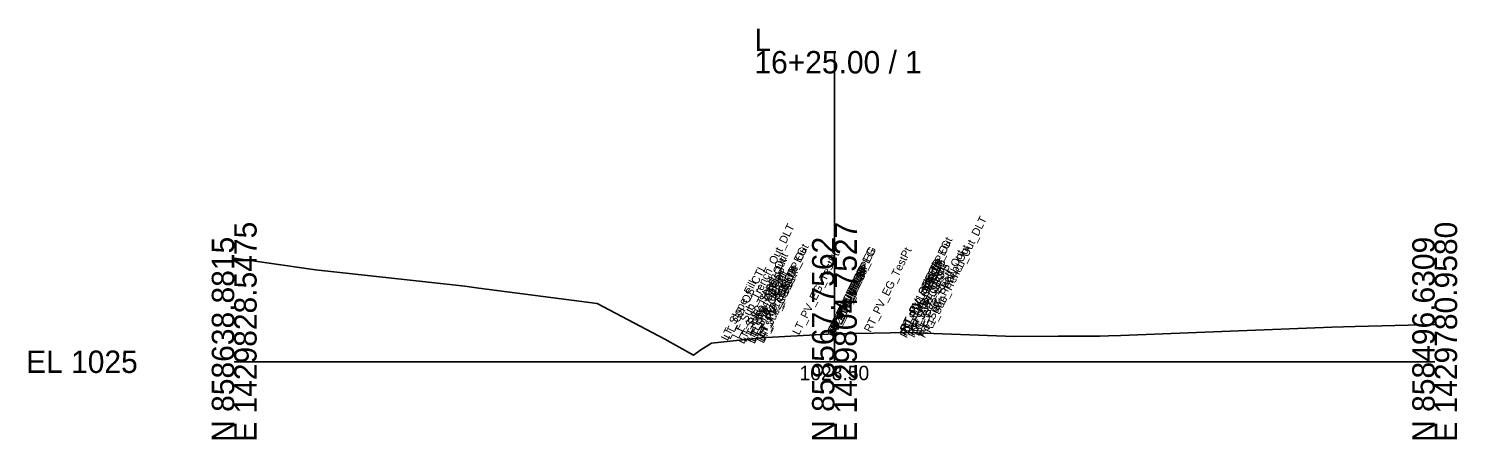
# Model space of a CAD drawing. Extents: x -26 to 176, y -10 to 13058.
# Drawn here: x -25.7 to 152.8, y 9490.3 to 9541.6 of the extents above; entities that cross this region are included whole.
import ezdxf

# ---------------------------------------------------------------- set-up
doc = ezdxf.new("R2010")
doc.units = 0
for name, color, linetype in [('Default', 7, 'Continuous'), ('Exist Cross Section Cell', 7, 'Continuous'), ('Exist XS Center Line Elevation Label', 7, 'Continuous'), ('Exist XS Ground Line', 7, 'Continuous'), ('Prop XS Dump Level', 7, 'Continuous')]:
    doc.layers.add(name, color=color, linetype=linetype)

msp = doc.modelspace()

# ---------------------------------------------------------------- linework, layer by layer
at = {"layer": 'Exist Cross Section Cell'}
for p, q in [((75, 9500), (75, 9538.8)), ((0, 9500), (75, 9500)), ((75, 9500), (150, 9500))]:
    msp.add_line(p, q, dxfattribs=at)
at = {"layer": 'Exist XS Ground Line'}
msp.add_lwpolyline([(0, 9512.93), (4.35, 9512.29), (10.14, 9511.47), (24.29, 9509.92), (28.8, 9509.45), (30.55, 9509.21), (45.36, 9507.29), (53.8, 9502.82), (57.37, 9500.84), (58.29, 9501.48), (59.65, 9502.32), (65.47, 9502.95), (66.08, 9503.02), (66.51, 9503.04), (74.92, 9503.49), (79.94, 9503.59), (84.01, 9503.67), (97.48, 9503.15), (102.94, 9503.18), (108.14, 9503.2), (109.24, 9503.22), (110.78, 9503.29), (124.43, 9503.83), (137.15, 9504.31), (140.05, 9504.4), (150, 9504.65)], dxfattribs=at)

# ---------------------------------------------------------------- texts
at = {"layer": 'Default'}
msp.add_text('-', height=0.0001, dxfattribs=at).set_placement((0, 9500))
at = {"layer": 'Exist Cross Section Cell'}
for s, p in [('L', (65, 9538.8)), ('16+25.00 / 1', (65, 9536)), ('EL 1025', (-26, 9498.6))]:
    msp.add_text(s, height=2.8, dxfattribs=at).set_placement(p)
for s, p in [('E 1429828.5475', (2.8, 9490)), ('E 1429804.7527', (77.8, 9490)), ('E 1429780.9580', (152.8, 9490)), ('N 858638.8815', (0, 9490)), ('N 858567.7562', (75, 9490)), ('N 858496.6309', (150, 9490))]:
    msp.add_text(s, height=2.8, rotation=90, dxfattribs=at).set_placement(p)
at = {"layer": 'Exist XS Center Line Elevation Label'}
msp.add_text('1028.50', height=1.8, dxfattribs=at).set_placement((70.64, 9497.7))
msp.add_text('1028.50', height=1.8, dxfattribs=at).set_placement((70.64, 9497.7))
msp.add_text('1028.50', height=1.8, dxfattribs=at).set_placement((70.64, 9497.7))
at = {"layer": 'Prop XS Dump Level'}
for s, p in [('RT_Sub_Trench_Out_DLT', (86.97, 9503.54)), ('LT_Sub_Trench_Out_DLT', (63.03, 9502.8)), ('LT_PV_OEEOP_EG', (66.14, 9503.02)), ('LT_PV_Sub_Tie_Out', (66.16, 9503.02)), ('RT_PV_IEEOP_EG', (75, 9503.5)), ('LT_PV_IEEOP_EG', (75, 9503.5)), ('RT_PV_EG_TestPt', (79.52, 9503.59)), ('RT_PV_Sub_Tie_Out', (84.02, 9503.67)), ('RT_PV_OEEOP_EG', (84.03, 9503.67)), ('RT_Sub_Trench_Out', (86.31, 9502.88)), ('LT_Sub_Trench_Out', (63.69, 9502.14)), ('LT_PS2_Shelf_Out', (63.95, 9502.39)), ('LT_PV1_OEEOP', (66.14, 9502.89)), ('LT_PV_EG_TestPt', (70.57, 9503.26)), ('RT_PV1_IEEOP', (75, 9503.37)), ('LT_PV1_IEEOP', (75, 9503.37)), ('RT_PV1_OEEOP', (84.03, 9503.55)), ('RT_PV2_OEEOP', (84.03, 9503.14)), ('RT_Sub_OEEOP', (84.03, 9502.89)), ('RT_PV1_OEOT', (85, 9503.7)), ('RT_PS1_OEOP', (85, 9503.7)), ('RT_PS2_Shelf_Out', (86.05, 9503.13)), ('LT_GS_OS_CTL', (62, 9502.72)), ('LT_PS2_OEOP', (64.45, 9502.4)), ('LT_PV1_OEOT', (65, 9502.96)), ('LT_PS1_OEOP', (65, 9502.96)), ('LT_PV2_OEOT', (65, 9502.42)), ('LT_Sub_OEOT', (65, 9502.17)), ('LT_PV2_OEEOP', (66.14, 9502.48)), ('LT_Sub_OEEOP', (66.14, 9502.23)), ('RT_PV2_IEEOP', (75, 9502.96)), ('LT_PV2_IEEOP', (75, 9502.96)), ('RT_PV2_OEOT', (85, 9503.16)), ('RT_Sub_OEOT', (85, 9502.91)), ('RT_PS2_OEOP', (85.55, 9503.14)), ('LT_Slope_Fill', (61.64, 9502.54)), ('PV1_PGL', (75, 9503.5)), ('PV2_PGL', (75, 9502.96))]:
    msp.add_text(s, height=1, rotation=63.5833, dxfattribs=at).set_placement(p)

doc.saveas('drawing.dxf')
